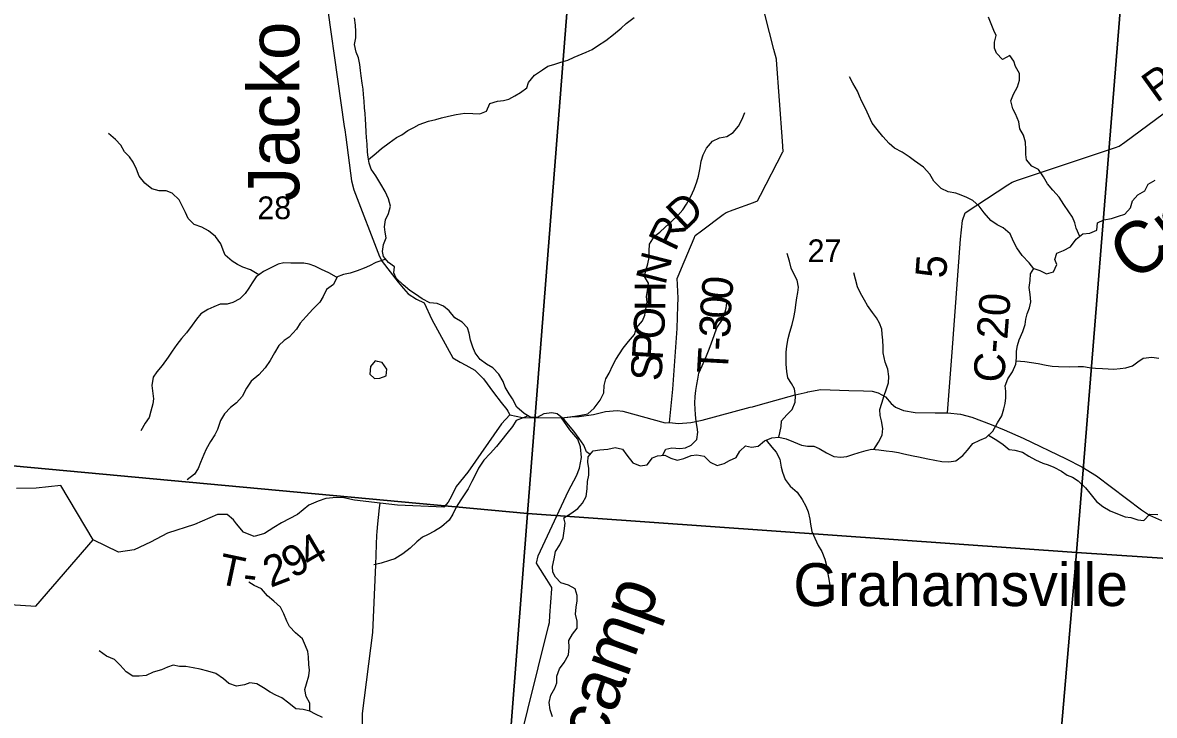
# Model space of a CAD drawing. Extents: x 1715311 to 2083412, y 146837 to 553079.
# Drawn here: x 1897277 to 1908281, y 347369 to 354105 of the extents above; entities that cross this region are included whole.
import ezdxf

# ---------------------------------------------------------------- set-up
doc = ezdxf.new("R2010")
doc.units = 0
for name, color, linetype in [('GM_X_County_Road', 7, 'Continuous'), ('GM_X_County_Road_Text', 7, 'Continuous'), ('GM_X_Minor_Lake', 7, 'Continuous'), ('GM_X_Minor_River', 7, 'Continuous'), ('GM_X_Minor_River_Text', 7, 'Continuous'), ('GM_X_Section', 7, 'Continuous'), ('GM_X_Section_Text', 7, 'Continuous'), ('GM_X_Township_Road', 7, 'Continuous'), ('GM_X_Township_Road_Text', 7, 'Continuous'), ('GM_X_Township_ROW', 7, 'Continuous'), ('GM_X_Unincorporated_Text', 7, 'Continuous')]:
    doc.layers.add(name, color=color, linetype=linetype)

msp = doc.modelspace()

# ---------------------------------------------------------------- linework, layer by layer
at = {"layer": 'GM_X_County_Road'}
for points in [[(1900181, 354688), (1900404, 353095), (1900408, 353062), (1900418, 352992), (1900474, 352568), (1900496, 352480), (1900746, 351831), (1900773, 351781), (1900927, 351582), (1900981, 351519), (1901027, 351469), (1901108, 351415), (1901180, 351379), (1901257, 351220), (1901460, 350845), (1901530, 350802), (1901587, 350773), (1901675, 350725), (1901759, 350642), (1901856, 350508), (1901930, 350411), (1901984, 350343), (1901993, 350328)], [(1906270, 350312), (1906316, 350901), (1906397, 352000), (1906417, 352181), (1906441, 352257), (1906855, 352527), (1906898, 352554), (1906950, 352572), (1907903, 352892), (1907940, 352905), (1907993, 352944), (1908591, 353382)], [(1901993, 350328), (1902014, 350291), (1902136, 350264), (1902515, 350262), (1902608, 350271), (1902687, 350274), (1902827, 350295), (1902945, 350324), (1903057, 350333), (1903113, 350326), (1903523, 350215), (1903566, 350218), (1903654, 350208), (1903774, 350218), (1903883, 350241), (1904352, 350365), (1904374, 350370), (1904453, 350391), (1904788, 350487), (1904904, 350512), (1904913, 350515), (1905038, 350538), (1905311, 350528), (1905452, 350525), (1905538, 350521), (1905597, 350506), (1905667, 350466), (1905722, 350400), (1905764, 350367), (1905843, 350332), (1905955, 350314), (1906149, 350310), (1906270, 350312)], [(1906270, 350312), (1906395, 350297), (1906507, 350268), (1906694, 350196), (1906822, 350147), (1907007, 350066), (1907422, 349865), (1907575, 349787), (1907718, 349697), (1908155, 349367), (1908233, 349316), (1908350, 349265)]]:
    msp.add_lwpolyline(points, dxfattribs=at)
at = {"layer": 'GM_X_Minor_Lake'}
for points in [[(1900726, 350810), (1900703, 350815), (1900659, 350761), (1900654, 350688), (1900697, 350645)], [(1900697, 350645), (1900751, 350649), (1900813, 350670), (1900819, 350736), (1900773, 350801), (1900726, 350810)]]:
    msp.add_lwpolyline(points, dxfattribs=at)
at = {"layer": 'GM_X_Minor_River'}
for points in [[(1902795, 349906), (1902759, 349930), (1902734, 349997), (1902688, 350061), (1902636, 350131), (1902585, 350195), (1902541, 350245), (1902475, 350300), (1902423, 350312), (1902343, 350302), (1902281, 350264), (1902217, 350267), (1902153, 350303), (1902082, 350365), (1902040, 350446), (1902008, 350496), (1901969, 350562), (1901949, 350614), (1901907, 350686), (1901848, 350748), (1901786, 350783), (1901724, 350829), (1901678, 350895), (1901655, 350949), (1901631, 351017), (1901619, 351086), (1901603, 351136), (1901550, 351194), (1901480, 351236), (1901424, 351302), (1901368, 351349), (1901307, 351373), (1901237, 351379), (1901163, 351420), (1901097, 351466), (1901041, 351500), (1900976, 351554), (1900910, 351621), (1900886, 351673), (1900892, 351731), (1900835, 351773), (1900787, 351831), (1900775, 351881), (1900787, 351949), (1900812, 352013), (1900802, 352067), (1900794, 352119), (1900804, 352187), (1900834, 352249), (1900855, 352321), (1900833, 352392), (1900801, 352464), (1900760, 352534), (1900710, 352614), (1900666, 352680), (1900646, 352738), (1900637, 352797), (1900631, 352847), (1900627, 352923), (1900619, 352989), (1900618, 353041), (1900614, 353113), (1900610, 353163), (1900606, 353221), (1900600, 353277), (1900597, 353341), (1900591, 353405), (1900587, 353457), (1900577, 353517), (1900568, 353587), (1900562, 353639), (1900556, 353698), (1900544, 353764), (1900519, 353818), (1900505, 353892), (1900515, 353956), (1900517, 354018), (1900512, 354080), (1900502, 354152)], [(1900641, 352774), (1900713, 352836), (1900765, 352880), (1900841, 352936), (1900913, 352988), (1900965, 353015), (1901023, 353057), (1901081, 353085), (1901131, 353115), (1901223, 353147), (1901293, 353162), (1901351, 353178), (1901417, 353194), (1901491, 353212), (1901577, 353225), (1901653, 353223), (1901721, 353219), (1901787, 353244), (1901821, 353320), (1901895, 353340), (1901953, 353348), (1902005, 353362), (1902063, 353394), (1902117, 353425), (1902179, 353471), (1902197, 353523), (1902254, 353595), (1902332, 353647), (1902384, 353681), (1902442, 353698), (1902510, 353720), (1902578, 353740), (1902640, 353770), (1902756, 353817), (1902814, 353845), (1902866, 353879), (1902948, 353931), (1903022, 353990), (1903096, 354052), (1903146, 354096), (1903222, 354156)], [(1907556, 352026), (1907521, 352106), (1907507, 352158), (1907486, 352214), (1907448, 352264), (1907402, 352336), (1907355, 352407), (1907295, 352475), (1907241, 352539), (1907204, 352605), (1907154, 352676), (1907090, 352710), (1907038, 352770), (1907031, 352822), (1907031, 352872), (1907029, 352942), (1907009, 353010), (1906974, 353073), (1906964, 353139), (1906930, 353217), (1906904, 353267), (1906887, 353345), (1906911, 353409), (1906949, 353481), (1906969, 353545), (1906970, 353611), (1906932, 353677), (1906914, 353729), (1906876, 353787), (1906806, 353746), (1906747, 353808), (1906727, 353858), (1906727, 353914), (1906743, 353980), (1906721, 354030), (1906694, 354094), (1906670, 354158)], [(1907108, 351712), (1907065, 351771), (1906995, 351842), (1906943, 351914), (1906910, 351978), (1906880, 352050), (1906812, 352110), (1906754, 352139), (1906691, 352181), (1906625, 352255), (1906579, 352320), (1906516, 352376), (1906458, 352406), (1906404, 352428), (1906350, 352446), (1906276, 352461), (1906208, 352493), (1906137, 352563), (1906097, 352630), (1906035, 352700), (1905948, 352762), (1905896, 352800), (1905828, 352845), (1905754, 352885), (1905701, 352929), (1905641, 352998), (1905585, 353066), (1905536, 353126), (1905504, 353200), (1905472, 353270), (1905438, 353337), (1905415, 353389), (1905393, 353439), (1905349, 353515), (1905316, 353577)], [(1902522, 350261), (1902571, 350269), (1902645, 350277), (1902705, 350287), (1902773, 350301), (1902835, 350356), (1902891, 350434), (1902927, 350506), (1902931, 350578), (1902948, 350642), (1902980, 350698), (1903016, 350774), (1903046, 350830), (1903080, 350884), (1903115, 350940), (1903169, 351004), (1903225, 351071), (1903245, 351137), (1903305, 351207), (1903328, 351261), (1903338, 351319), (1903348, 351387), (1903344, 351441), (1903352, 351499), (1903361, 351573), (1903325, 351637), (1903339, 351705), (1903357, 351759), (1903370, 351821), (1903370, 351883), (1903372, 351951), (1903420, 352029), (1903472, 352067), (1903524, 352115), (1903593, 352177), (1903647, 352231), (1903697, 352284), (1903733, 352340), (1903775, 352414), (1903807, 352486), (1903832, 352558), (1903848, 352612), (1903864, 352692), (1903876, 352758), (1903895, 352818), (1903925, 352886), (1903985, 352954), (1904053, 352986), (1904123, 352999), (1904185, 353037), (1904237, 353099), (1904273, 353167), (1904298, 353231)], [(1899574, 351653), (1899492, 351702), (1899418, 351726), (1899366, 351753), (1899313, 351785), (1899247, 351843), (1899227, 351893), (1899203, 351955), (1899152, 352026), (1899084, 352082), (1899020, 352116), (1898944, 352143), (1898887, 352199), (1898861, 352259), (1898835, 352311), (1898799, 352381), (1898732, 352446), (1898672, 352470), (1898604, 352468), (1898534, 352488), (1898466, 352543), (1898411, 352613), (1898383, 352679), (1898353, 352749), (1898316, 352799), (1898266, 352850), (1898230, 352912), (1898180, 352968), (1898111, 353028)], [(1905793, 349925), (1905845, 349913), (1905937, 349892), (1905989, 349884), (1906079, 349864), (1906145, 349851), (1906215, 349837), (1906284, 349833), (1906352, 349845), (1906420, 349896), (1906463, 349948), (1906515, 350012), (1906585, 350046), (1906647, 350070), (1906709, 350134), (1906755, 350213), (1906797, 350281), (1906818, 350349), (1906830, 350403), (1906838, 350457), (1906838, 350523), (1906832, 350573), (1906857, 350643), (1906903, 350711), (1906933, 350783), (1906941, 350845), (1906942, 350909), (1906950, 350967), (1906966, 351021), (1907002, 351103), (1907024, 351171), (1907031, 351221), (1907045, 351273), (1907067, 351333), (1907081, 351391), (1907073, 351463), (1907064, 351531), (1907072, 351599), (1907078, 351663), (1907110, 351715), (1907168, 351695), (1907232, 351661), (1907300, 351682), (1907332, 351752), (1907312, 351802), (1907333, 351864), (1907399, 351890), (1907467, 351924), (1907521, 351998), (1907587, 352051), (1907655, 352059), (1907721, 352087), (1907727, 352159), (1907789, 352189), (1907863, 352201), (1907931, 352224), (1907995, 352242), (1908049, 352304), (1908068, 352372), (1908122, 352432), (1908188, 352468), (1908220, 352533), (1908288, 352573)], [(1904630, 350073), (1904638, 350117), (1904652, 350179), (1904654, 350233), (1904708, 350293), (1904758, 350343), (1904790, 350413), (1904793, 350477), (1904783, 350545), (1904753, 350597), (1904717, 350651), (1904706, 350714), (1904702, 350784), (1904700, 350846), (1904700, 350902), (1904707, 350958), (1904719, 351034), (1904737, 351094), (1904759, 351170), (1904776, 351238), (1904790, 351306), (1904796, 351360), (1904806, 351430), (1904814, 351482), (1904821, 351532), (1904809, 351602), (1904779, 351656), (1904751, 351718), (1904732, 351786), (1904710, 351860)], [(1900808, 351806), (1900711, 351772), (1900649, 351740), (1900599, 351716), (1900529, 351692), (1900463, 351668), (1900395, 351655), (1900327, 351631), (1900253, 351671), (1900183, 351706), (1900117, 351738), (1900064, 351756), (1900012, 351766), (1899886, 351767), (1899816, 351769), (1899762, 351757), (1899704, 351727), (1899620, 351686), (1899548, 351634), (1899510, 351574), (1899475, 351522), (1899439, 351470), (1899389, 351420), (1899321, 351383), (1899267, 351367), (1899197, 351367), (1899137, 351343), (1899077, 351315), (1899009, 351274), (1898967, 351222), (1898925, 351164), (1898871, 351090), (1898822, 351034), (1898776, 350974), (1898730, 350911), (1898692, 350853), (1898632, 350771), (1898580, 350711), (1898545, 350657), (1898533, 350575), (1898539, 350525), (1898549, 350447), (1898542, 350397), (1898522, 350327), (1898506, 350267), (1898468, 350209), (1898426, 350135)], [(1900334, 351634), (1900298, 351559), (1900232, 351511), (1900200, 351441), (1900166, 351387), (1900100, 351320), (1900034, 351248), (1899976, 351184), (1899941, 351124), (1899869, 351048), (1899819, 351014), (1899769, 350967), (1899727, 350893), (1899683, 350821), (1899634, 350747), (1899572, 350679), (1899498, 350619), (1899452, 350550), (1899410, 350470), (1899355, 350408), (1899299, 350364), (1899241, 350302), (1899201, 350236), (1899171, 350148), (1899147, 350096), (1899104, 350032), (1899060, 349957), (1899038, 349905), (1899006, 349827), (1898984, 349769), (1898949, 349713), (1898877, 349659)], [(1905553, 349955), (1905600, 350024), (1905634, 350094), (1905640, 350160), (1905629, 350234), (1905615, 350286), (1905613, 350344), (1905631, 350406), (1905654, 350478), (1905672, 350534), (1905696, 350604), (1905700, 350664), (1905691, 350736), (1905665, 350802), (1905645, 350894), (1905645, 350950), (1905642, 351018), (1905636, 351076), (1905630, 351126), (1905610, 351184), (1905579, 351235), (1905541, 351285), (1905493, 351355), (1905463, 351407), (1905424, 351475), (1905396, 351537), (1905374, 351612), (1905360, 351672)], [(1903497, 349897), (1903530, 349958), (1903590, 349969), (1903666, 349965), (1903722, 349971), (1903778, 349995), (1903832, 350052), (1903843, 350122), (1903835, 350172), (1903827, 350227), (1903819, 350295), (1903815, 350345), (1903814, 350405), (1903816, 350471), (1903824, 350527), (1903832, 350585), (1903843, 350637), (1903851, 350697), (1903883, 350767), (1903925, 350865), (1903953, 350931), (1903976, 350992), (1904000, 351064), (1904028, 351136), (1904074, 351210), (1904101, 351268), (1904117, 351330), (1904123, 351380)], [(1906937, 350816), (1907021, 350809), (1907085, 350799), (1907151, 350790), (1907229, 350774), (1907287, 350764), (1907348, 350760), (1907456, 350759), (1907540, 350761), (1907592, 350761), (1907648, 350752), (1907708, 350746), (1907778, 350742), (1907832, 350740), (1907888, 350737), (1907948, 350741), (1908004, 350747), (1908070, 350767), (1908122, 350807), (1908172, 350842), (1908256, 350852), (1908326, 350842)], [(1902193, 350281), (1902145, 350261), (1902077, 350235), (1902041, 350179), (1901985, 350110), (1901937, 350048), (1901883, 349984), (1901822, 349914), (1901762, 349850), (1901710, 349772), (1901674, 349698), (1901644, 349642), (1901609, 349573), (1901537, 349465), (1901491, 349395), (1901459, 349325), (1901423, 349267), (1901348, 349201), (1901282, 349160), (1901214, 349124), (1901164, 349102), (1901110, 349058), (1901044, 348996), (1900974, 348941), (1900896, 348891), (1900844, 348875), (1900762, 348849), (1900690, 348832)], [(1902430, 347356), (1902406, 347422), (1902395, 347494), (1902413, 347566), (1902453, 347632), (1902471, 347684), (1902470, 347750), (1902498, 347820), (1902542, 347884), (1902586, 347958), (1902590, 348028), (1902589, 348098), (1902623, 348160), (1902669, 348218), (1902669, 348284), (1902654, 348354), (1902658, 348420), (1902670, 348484), (1902668, 348534), (1902649, 348598), (1902585, 348634), (1902509, 348657), (1902459, 348713), (1902431, 348763), (1902430, 348815), (1902446, 348891), (1902458, 348961), (1902500, 349027), (1902533, 349095), (1902541, 349165), (1902553, 349239), (1902539, 349289), (1902607, 349333), (1902675, 349380), (1902722, 349432), (1902756, 349498), (1902766, 349572), (1902770, 349642), (1902782, 349706), (1902781, 349770), (1902771, 349832), (1902775, 349882), (1902823, 349940), (1902889, 349952), (1902967, 349958), (1903037, 349973), (1903111, 349959), (1903153, 349899), (1903210, 349825), (1903280, 349794), (1903350, 349806), (1903400, 349872), (1903450, 349892), (1903522, 349899), (1903578, 349869), (1903642, 349849), (1903706, 349867), (1903778, 349895), (1903832, 349902), (1903904, 349890), (1903961, 349830), (1904029, 349799), (1904097, 349817), (1904149, 349847), (1904215, 349875), (1904249, 349939), (1904306, 349989), (1904363, 349976), (1904429, 349986), (1904489, 350038), (1904561, 350068), (1904631, 350073), (1904701, 350057), (1904773, 350029), (1904849, 349996), (1904907, 349986), (1904969, 349986), (1905023, 349964), (1905094, 349922), (1905164, 349887), (1905232, 349879), (1905290, 349887), (1905350, 349907), (1905412, 349924), (1905480, 349944), (1905532, 349956), (1905602, 349952), (1905672, 349941), (1905734, 349935), (1905793, 349925)], [(1906670, 350094), (1906749, 350045), (1906810, 350003), (1906870, 349953), (1906926, 349949), (1906998, 349928), (1907060, 349890), (1907127, 349854), (1907197, 349823), (1907249, 349805), (1907305, 349781), (1907379, 349745), (1907432, 349704), (1907486, 349686), (1907540, 349648), (1907612, 349580), (1907654, 349530), (1907717, 349449), (1907781, 349399), (1907851, 349359), (1907924, 349328), (1907996, 349300), (1908054, 349294), (1908120, 349272), (1908180, 349263), (1908236, 349325), (1908316, 349321)], [(1904507, 350045), (1904563, 349978), (1904603, 349927), (1904639, 349859), (1904652, 349783), (1904664, 349733), (1904692, 349663), (1904740, 349599), (1904807, 349538), (1904857, 349468), (1904893, 349402), (1904914, 349348), (1904930, 349278), (1904938, 349228), (1904952, 349158), (1904981, 349091), (1905013, 349021), (1905047, 348961), (1905076, 348889), (1905096, 348813), (1905104, 348763), (1905112, 348711), (1905122, 348653), (1905131, 348589), (1905135, 348526), (1905131, 348462)], [(1900069, 347411), (1900068, 347489), (1900034, 347551), (1900022, 347621), (1900038, 347675), (1900059, 347753), (1900065, 347809), (1900061, 347865), (1900057, 347939), (1900050, 347990), (1900028, 348046), (1899998, 348114), (1899930, 348170), (1899873, 348234), (1899847, 348284), (1899815, 348357), (1899784, 348421), (1899720, 348481), (1899656, 348531), (1899600, 348598), (1899529, 348632), (1899477, 348664)], [(1900191, 347349), (1900123, 347381), (1900069, 347411), (1900006, 347425), (1899932, 347434), (1899864, 347488), (1899796, 347538), (1899738, 347564), (1899683, 347595), (1899619, 347637), (1899555, 347677), (1899485, 347687), (1899435, 347666), (1899355, 347652), (1899283, 347680), (1899230, 347724), (1899154, 347777), (1899076, 347799), (1899004, 347817), (1898934, 347830), (1898865, 347844), (1898801, 347844), (1898739, 347856), (1898685, 347839), (1898627, 347811), (1898547, 347789), (1898479, 347757), (1898411, 347750), (1898347, 347750), (1898283, 347792), (1898225, 347858), (1898170, 347911), (1898092, 347945), (1898020, 347997)]]:
    msp.add_lwpolyline(points, dxfattribs=at)
at = {"layer": 'GM_X_Section'}
for points in [[(1902626, 354942), (1902187, 349333), (1896827, 349829), (1897276, 355350)], [(1907976, 354545), (1907523, 348954), (1902187, 349333), (1902626, 354942)], [(1913462, 354034), (1912974, 348592), (1907523, 348954), (1907976, 354545)], [(1896827, 349829), (1902187, 349333), (1901774, 344007), (1896416, 344416), (1896200, 344435)], [(1902187, 349333), (1907523, 348954), (1907064, 343582), (1902306, 343958), (1901774, 344007)], [(1907523, 348954), (1912974, 348592), (1912507, 343127), (1907496, 343547), (1907064, 343582)]]:
    msp.add_lwpolyline(points, close=True, dxfattribs=at)
at = {"layer": 'GM_X_Township_Road'}
for points in [[(1903566, 350218), (1903600, 350540), (1903640, 351130), (1903649, 351352), (1903652, 351425), (1903642, 351619), (1903643, 351624), (1903683, 351716), (1903806, 352008), (1903817, 352035), (1903879, 352081), (1904089, 352239), (1904116, 352259), (1904184, 352284), (1904382, 352357), (1904422, 352372), (1904451, 352427), (1904670, 352848), (1904673, 352853), (1904665, 352953), (1904607, 353742), (1904607, 353749), (1904582, 353845), (1904451, 354356)], [(1902014, 350291), (1901933, 350203), (1901604, 349734), (1901493, 349593), (1901446, 349500), (1901415, 349442), (1901373, 349394), (1900921, 349414), (1900753, 349433), (1900503, 349462), (1900399, 349483), (1900329, 349486), (1900225, 349479), (1900151, 349451), (1900059, 349414), (1899948, 349321), (1899795, 349240), (1899720, 349195), (1899628, 349138), (1899529, 349107), (1899424, 349152), (1899356, 349232), (1899327, 349269), (1899267, 349321), (1899173, 349322), (1898948, 349226), (1898685, 349141), (1898520, 349052), (1898360, 348979), (1898209, 348955), (1897961, 349077)], [(1902090, 347022), (1902391, 348237), (1902399, 348271), (1902404, 348340), (1902422, 348599), (1902423, 348613), (1902375, 348690), (1902291, 348822), (1902273, 348850), (1902288, 348919), (1902583, 349552), (1902662, 349697), (1902692, 349774), (1902710, 349878), (1902701, 349979), (1902674, 350056), (1902597, 350147), (1902515, 350262)], [(1897961, 349077), (1897647, 349603), (1897408, 349579), (1897218, 349576)], [(1900722, 349125), (1900723, 349151), (1900728, 349198), (1900748, 349386), (1900753, 349433)], [(1891378, 348808), (1894063, 348655), (1895248, 348576), (1895393, 348613), (1895455, 348621), (1895573, 348594), (1895797, 348535), (1897406, 348431), (1897961, 349077)]]:
    msp.add_lwpolyline(points, dxfattribs=at)
at = {"layer": 'GM_X_Township_ROW'}
msp.add_lwpolyline([(1900486, 345586), (1900509, 346060), (1900590, 346779), (1900580, 347386), (1900681, 348175), (1900711, 348832), (1900722, 349125)], dxfattribs=at)

# ---------------------------------------------------------------- texts
at = {"layer": 'GM_X_County_Road_Text'}
for s, rotation, p in [('P', 35.72, (1908301, 353319)), ('5', 85.917, (1906255, 351613)), ('C-20', 85.5458, (1906818, 350597))]:
    msp.add_text(s, height=300, rotation=rotation, dxfattribs=at).set_placement(p)
at = {"layer": 'GM_X_Minor_River_Text'}
for s, height, rotation, p in [('Jacko', 500.1, 90.0001, (1899967, 352367)), ('Creek', 500, 36.0028, (1908079, 351574)), ('Sugarcamp', 500, 69.9991, (1902304, 345386))]:
    msp.add_text(s, height=height, rotation=rotation, dxfattribs=at).set_placement(p)
at = {"layer": 'GM_X_Section_Text'}
for s, p in [('28', (1899559, 352194)), ('27', (1904909, 351776))]:
    msp.add_text(s, height=221, rotation=0, dxfattribs=at).set_placement(p)
at = {"layer": 'GM_X_Township_Road_Text'}
for s, rotation, p in [('D', 43.1451, (1903711, 352069)), ('R', 64.2396, (1903621, 351870)), ('N', 75.6996, (1903526, 351544)), ('0', 83.9627, (1904171, 351402)), ('H', 89.5757, (1903527, 351299)), ('0', 87.3254, (1904163, 351222)), ('O', 86.7104, (1903511, 351019)), ('3', 86.9087, (1904153, 351035)), ('P', 86.6006, (1903499, 350816)), ('T', 86.8057, (1904133, 350687)), ('-', 86.8175, (1904146, 350911)), ('S', 86.6053, (1903487, 350614)), ('4', 30.6011, (1900069, 348789)), ('9', 29.6562, (1899903, 348695)), ('T', 348.0295, (1899159, 348654)), ('2', 21.0819, (1899687, 348608)), ('-', 353.3237, (1899409, 348602))]:
    msp.add_text(s, height=300, rotation=rotation, dxfattribs=at).set_placement(p)
at = {"layer": 'GM_X_Unincorporated_Text'}
msp.add_text('Grahamsville', height=417, rotation=0, dxfattribs=at).set_placement((1904771, 348432))

doc.saveas('drawing.dxf')
